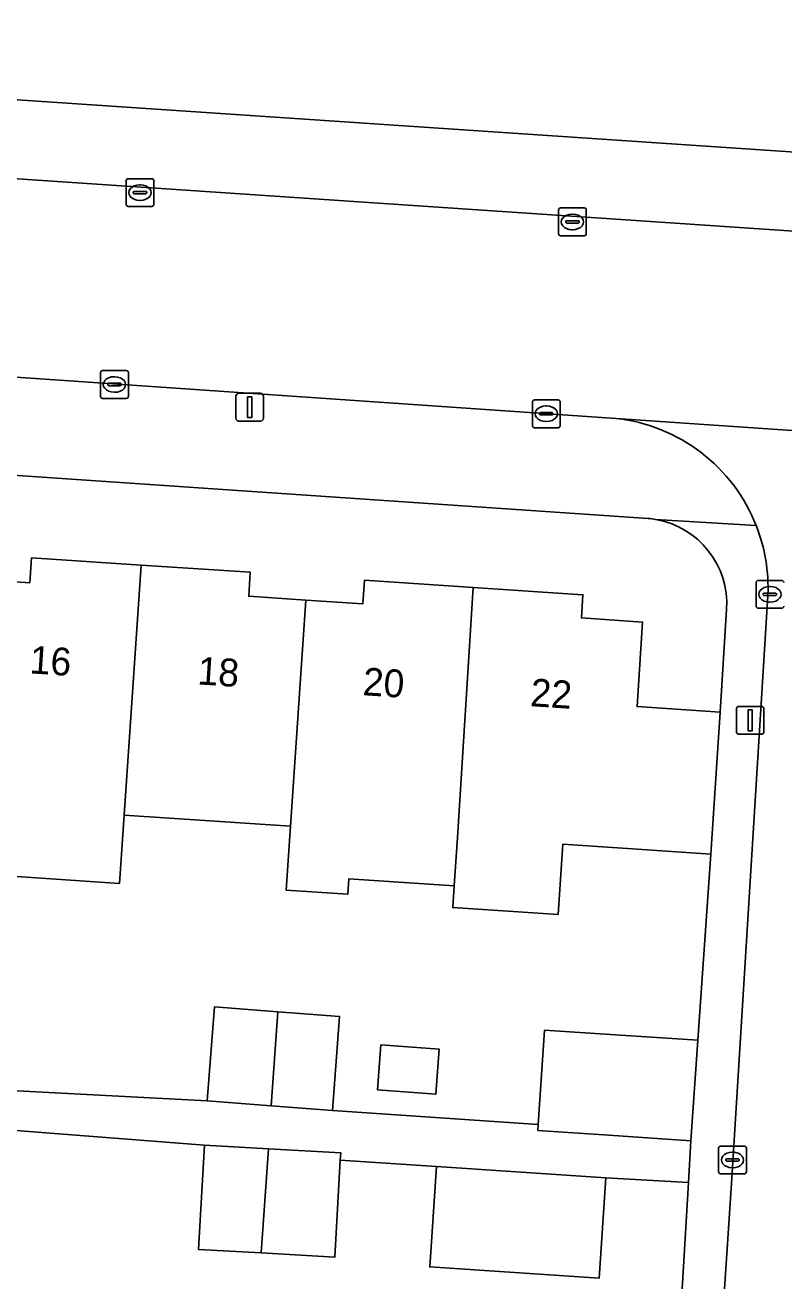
# Model space of a CAD drawing. Extents: x 161848 to 162726, y 385382 to 386521.
# Drawn here: x 162288.48 to 162315.79, y 385563.71 to 385608.89 of the extents above; entities that cross this region are included whole.
import ezdxf

# ---------------------------------------------------------------- set-up
doc = ezdxf.new("R2010")
doc.units = 0
for name, color, linetype in [('IMGEO_Erf', 7, 'Continuous'), ('IMGEO_Groenvoorziening', 7, 'Continuous'), ('IMGEO_Kolk', 7, 'Continuous'), ('IMGEO_Lichtmast', 7, 'Continuous'), ('IMGEO_Muur', 7, 'Continuous'), ('IMGEO_Pand', 7, 'Continuous'), ('IMGEO_Pand_nummerreeks', 7, 'Continuous'), ('IMGEO_Rijbaan_lokaal_open', 7, 'Continuous'), ('IMGEO_Voetpad_open', 7, 'Continuous')]:
    doc.layers.add(name, color=color, linetype=linetype)

msp = doc.modelspace()

# ---------------------------------------------------------------- linework, layer by layer
at = {"layer": 'IMGEO_Erf'}
for points in [[(162310.902, 385591.138), (162245.477, 385595.597), (162240.397, 385595.895)], [(162286.584, 385588.962), (162288.657, 385588.824), (162288.716, 385589.724), (162292.662, 385589.463), (162296.586, 385589.204), (162296.529, 385588.34), (162298.583, 385588.204), (162300.64, 385588.068), (162300.696, 385588.917), (162304.608, 385588.658), (162308.555, 385588.397), (162308.499, 385587.559), (162310.703, 385587.413), (162310.502, 385584.37), (162313.495, 385584.171), (162313.724, 385587.868)], [(162287.968, 385570.566), (162295.039, 385570.185), (162295.298, 385573.567), (162297.573, 385573.393), (162299.802, 385573.222), (162299.543, 385569.841), (162306.95, 385569.344), (162307.175, 385572.737), (162309.726, 385572.567), (162312.69, 385572.369), (162313.157, 385579.065), (162310.164, 385579.263), (162307.829, 385579.417), (162307.662, 385576.893), (162303.872, 385577.144), (162303.923, 385577.92), (162300.133, 385578.179), (162300.095, 385577.619), (162297.872, 385577.77), (162298.028, 385580.065), (162292.044, 385580.461), (162291.876, 385578.007), (162285.874, 385578.411)], [(162312.144, 385563.613), (162312.352, 385567.255), (162309.381, 385567.425), (162309.141, 385563.813), (162303.044, 385564.218), (162303.284, 385567.83), (162299.826, 385568.05), (162299.633, 385564.57), (162296.983, 385564.717), (162294.726, 385564.842), (162294.934, 385568.591), (162287.846, 385569.148)]]:
    msp.add_lwpolyline(points, dxfattribs=at)
msp.add_lwpolyline([(162301.285, 385572.204), (162303.384, 385572.044), (162303.26, 385570.426), (162301.161, 385570.586)], close=True, dxfattribs=at)
for centre, radius, start, end in [((162310.649, 385588.037), 3.112, 80.3164, 85.3291), ((162310.65, 385588.068), 3.08, 356.271, 80.2496)]:
    msp.add_arc(centre, radius, start, end, dxfattribs=at)
at = {"layer": 'IMGEO_Groenvoorziening'}
msp.add_lwpolyline([(162313.914, 385618.371), (162310.525, 385618.197), (162307.227, 385618.391), (162299.207, 385618.52), (162290.024, 385619.62), (162287.372, 385623.112), (162282.522, 385621.172), (162278.641, 385622.853), (162272.521, 385624.409), (162263.398, 385624.644), (162261.506, 385623.382), (162259.85, 385621.49), (162259.535, 385620.15), (162259.693, 385616.365), (162261.033, 385614.788), (162265.291, 385613.054), (162271.835, 385611.556), (162272.639, 385611.354), (162274.554, 385609.13), (162276.436, 385606.992), (162319.231, 385604.108), (162319.8, 385609.337), (162317.424, 385614.541)], close=True, dxfattribs=at)
at = {"layer": 'IMGEO_Kolk'}
for p, q in [((162292.118, 385602.436), (162292.118, 385603.288)), ((162292.193, 385603.362), (162293.045, 385603.362)), ((162292.606, 385603.142), (162292.631, 385603.142)), ((162293.119, 385603.288), (162293.119, 385602.436)), ((162292.377, 385602.856), (162292.377, 385602.868)), ((162292.815, 385602.819), (162292.417, 385602.819)), ((162292.42, 385602.905), (162292.818, 385602.905)), ((162292.629, 385602.582), (162292.604, 385602.582)), ((162292.861, 385602.868), (162292.861, 385602.856)), ((162293.045, 385602.362), (162292.193, 385602.362)), ((162307.677, 385601.381), (162307.677, 385602.233)), ((162307.752, 385602.307), (162308.604, 385602.307)), ((162308.165, 385602.087), (162308.19, 385602.087)), ((162308.678, 385602.233), (162308.678, 385601.381)), ((162307.936, 385601.801), (162307.936, 385601.813)), ((162308.374, 385601.764), (162307.976, 385601.764)), ((162307.979, 385601.85), (162308.377, 385601.85)), ((162308.42, 385601.813), (162308.42, 385601.801)), ((162308.604, 385601.307), (162307.752, 385601.307)), ((162308.188, 385601.527), (162308.163, 385601.527)), ((162291.198, 385595.532), (162291.198, 385596.384)), ((162291.273, 385596.458), (162292.125, 385596.458)), ((162291.686, 385596.238), (162291.711, 385596.238)), ((162292.199, 385596.384), (162292.199, 385595.532)), ((162291.457, 385595.952), (162291.457, 385595.964)), ((162291.895, 385595.915), (162291.497, 385595.915)), ((162291.5, 385596.001), (162291.898, 385596.001)), ((162291.941, 385595.964), (162291.941, 385595.952)), ((162292.125, 385595.458), (162291.273, 385595.458)), ((162291.709, 385595.678), (162291.684, 385595.678)), ((162306.738, 385594.479), (162306.738, 385595.331)), ((162306.813, 385595.405), (162307.665, 385595.405)), ((162307.739, 385595.331), (162307.739, 385594.479)), ((162306.997, 385594.899), (162306.997, 385594.911)), ((162307.435, 385594.862), (162307.037, 385594.862)), ((162307.04, 385594.948), (162307.438, 385594.948)), ((162307.226, 385595.185), (162307.251, 385595.185)), ((162307.481, 385594.911), (162307.481, 385594.899)), ((162307.665, 385594.405), (162306.813, 385594.405)), ((162307.249, 385594.625), (162307.224, 385594.625)), ((162314.786, 385587.983), (162314.786, 385588.835)), ((162314.861, 385588.909), (162315.713, 385588.909)), ((162315.274, 385588.689), (162315.299, 385588.689)), ((162315.045, 385588.403), (162315.045, 385588.415)), ((162315.483, 385588.366), (162315.085, 385588.366)), ((162315.088, 385588.452), (162315.486, 385588.452)), ((162315.297, 385588.129), (162315.272, 385588.129)), ((162315.529, 385588.415), (162315.529, 385588.403)), ((162315.713, 385587.909), (162314.861, 385587.909)), ((162313.438, 385567.637), (162313.438, 385568.489)), ((162313.513, 385568.563), (162314.365, 385568.563)), ((162313.926, 385568.343), (162313.951, 385568.343)), ((162314.439, 385568.489), (162314.439, 385567.637)), ((162313.697, 385568.057), (162313.697, 385568.069)), ((162314.135, 385568.02), (162313.737, 385568.02)), ((162313.74, 385568.106), (162314.138, 385568.106)), ((162313.949, 385567.783), (162313.924, 385567.783)), ((162314.181, 385568.069), (162314.181, 385568.057)), ((162314.365, 385567.563), (162313.513, 385567.563))]:
    msp.add_line(p, q, dxfattribs=at)
for points in [[(162292.118, 385602.436), (162292.118, 385603.288)], [(162292.193, 385603.362), (162293.045, 385603.362)], [(162293.119, 385603.288), (162293.119, 385602.436)], [(162293.045, 385602.362), (162292.193, 385602.362)], [(162307.677, 385601.381), (162307.677, 385602.233)], [(162307.752, 385602.307), (162308.604, 385602.307)], [(162308.678, 385602.233), (162308.678, 385601.381)], [(162308.604, 385601.307), (162307.752, 385601.307)], [(162291.198, 385595.532), (162291.198, 385596.384)], [(162291.273, 385596.458), (162292.125, 385596.458)], [(162292.199, 385596.384), (162292.199, 385595.532)], [(162292.125, 385595.458), (162291.273, 385595.458)], [(162306.738, 385594.479), (162306.738, 385595.331)], [(162306.813, 385595.405), (162307.665, 385595.405)], [(162307.739, 385595.331), (162307.739, 385594.479)], [(162307.665, 385594.405), (162306.813, 385594.405)], [(162314.786, 385587.983), (162314.786, 385588.835)], [(162314.861, 385588.909), (162315.713, 385588.909)], [(162315.713, 385587.909), (162314.861, 385587.909)], [(162313.438, 385567.637), (162313.438, 385568.489)], [(162313.513, 385568.563), (162314.365, 385568.563)], [(162314.439, 385568.489), (162314.439, 385567.637)], [(162314.365, 385567.563), (162313.513, 385567.563)]]:
    msp.add_lwpolyline(points, dxfattribs=at)
for centre, radius, start, end in [((162292.195, 385603.286), 0.0765, 91.552, 178.448), ((162292.195, 385603.286), 0.0765, 91.552, 178.448), ((162293.043, 385603.286), 0.0765, 1.552, 88.448), ((162293.043, 385603.286), 0.0765, 1.552, 88.448), ((162292.417, 385602.865), 0.0403, 85.8775, 175.7526), ((162292.414, 385602.855), 0.0366, 178.938, 274.7102), ((162292.818, 385602.862), 0.043, 264.8664, 352.4533), ((162292.822, 385602.867), 0.0386, 1.7309, 96.639), ((162292.195, 385602.438), 0.0765, 181.552, 268.448), ((162292.195, 385602.438), 0.0765, 181.552, 268.448), ((162293.043, 385602.438), 0.0765, 271.552, 358.448), ((162293.043, 385602.438), 0.0765, 271.552, 358.448), ((162307.754, 385602.231), 0.0765, 91.552, 178.448), ((162307.754, 385602.231), 0.0765, 91.552, 178.448), ((162308.602, 385602.231), 0.0765, 1.552, 88.448), ((162308.602, 385602.231), 0.0765, 1.552, 88.448), ((162307.976, 385601.81), 0.0403, 85.8775, 175.7526), ((162307.973, 385601.8), 0.0366, 178.938, 274.7102), ((162308.377, 385601.807), 0.043, 264.8664, 352.4533), ((162308.381, 385601.812), 0.0386, 1.7309, 96.639), ((162307.754, 385601.383), 0.0765, 181.552, 268.448), ((162307.754, 385601.383), 0.0765, 181.552, 268.448), ((162308.602, 385601.383), 0.0765, 271.552, 358.448), ((162308.602, 385601.383), 0.0765, 271.552, 358.448), ((162291.275, 385596.382), 0.0765, 91.552, 178.448), ((162291.275, 385596.382), 0.0765, 91.552, 178.448), ((162292.123, 385596.382), 0.0765, 1.552, 88.448), ((162292.123, 385596.382), 0.0765, 1.552, 88.448), ((162291.497, 385595.961), 0.0403, 85.8775, 175.7526), ((162291.494, 385595.951), 0.0366, 178.938, 274.7102), ((162291.898, 385595.958), 0.043, 264.8664, 352.4533), ((162291.902, 385595.963), 0.0386, 1.7309, 96.639), ((162291.275, 385595.534), 0.0765, 181.552, 268.448), ((162291.275, 385595.534), 0.0765, 181.552, 268.448), ((162292.123, 385595.534), 0.0765, 271.552, 358.448), ((162292.123, 385595.534), 0.0765, 271.552, 358.448), ((162306.815, 385595.329), 0.0765, 91.552, 178.448), ((162306.815, 385595.329), 0.0765, 91.552, 178.448), ((162307.663, 385595.329), 0.0765, 1.552, 88.448), ((162307.663, 385595.329), 0.0765, 1.552, 88.448), ((162307.037, 385594.908), 0.0403, 85.8775, 175.7526), ((162307.034, 385594.898), 0.0366, 178.938, 274.7102), ((162307.438, 385594.905), 0.043, 264.8664, 352.4533), ((162307.442, 385594.91), 0.0386, 1.7309, 96.639), ((162306.815, 385594.481), 0.0765, 181.552, 268.448), ((162306.815, 385594.481), 0.0765, 181.552, 268.448), ((162307.663, 385594.481), 0.0765, 271.552, 358.448), ((162307.663, 385594.481), 0.0765, 271.552, 358.448), ((162314.863, 385588.833), 0.0765, 91.552, 178.448), ((162314.863, 385588.833), 0.0765, 91.552, 178.448), ((162315.711, 385588.833), 0.0765, 1.552, 88.448), ((162315.711, 385588.833), 0.0765, 1.552, 88.448), ((162315.085, 385588.412), 0.0403, 85.8775, 175.7526), ((162315.082, 385588.402), 0.0366, 178.938, 274.7102), ((162315.486, 385588.409), 0.043, 264.8664, 352.4533), ((162315.49, 385588.414), 0.0386, 1.7309, 96.639), ((162314.863, 385587.985), 0.0765, 181.552, 268.448), ((162314.863, 385587.985), 0.0765, 181.552, 268.448), ((162315.711, 385587.985), 0.0765, 271.552, 358.448), ((162315.711, 385587.985), 0.0765, 271.552, 358.448), ((162313.515, 385568.487), 0.0765, 91.552, 178.448), ((162313.515, 385568.487), 0.0765, 91.552, 178.448), ((162314.363, 385568.487), 0.0765, 1.552, 88.448), ((162314.363, 385568.487), 0.0765, 1.552, 88.448), ((162313.737, 385568.066), 0.0403, 85.8775, 175.7526), ((162313.734, 385568.056), 0.0366, 178.938, 274.7102), ((162314.138, 385568.063), 0.043, 264.8664, 352.4533), ((162314.142, 385568.068), 0.0386, 1.7309, 96.639), ((162313.515, 385567.639), 0.0765, 181.552, 268.448), ((162313.515, 385567.639), 0.0765, 181.552, 268.448), ((162314.363, 385567.639), 0.0765, 271.552, 358.448), ((162314.363, 385567.639), 0.0765, 271.552, 358.448)]:
    msp.add_arc(centre, radius, start, end, dxfattribs=at)
for centre, major_axis, ratio, start_param, end_param in [((162292.605, 385602.862), (-0.387, 0.002), 0.722429, 4.712389, 7.853982), ((162292.63, 385602.862), (-0.39, 0.002), 0.717154, 1.570796, 4.712389), ((162308.164, 385601.807), (-0.387, 0.002), 0.722429, 4.712389, 7.853982), ((162308.189, 385601.807), (-0.39, 0.002), 0.717154, 1.570796, 4.712389), ((162291.685, 385595.958), (-0.387, 0.002), 0.722429, 4.712389, 7.853982), ((162291.71, 385595.958), (-0.39, 0.002), 0.717154, 1.570796, 4.712389), ((162307.225, 385594.905), (-0.387, 0.002), 0.722429, 4.712389, 7.853982), ((162307.25, 385594.905), (-0.39, 0.002), 0.717154, 1.570796, 4.712389), ((162315.273, 385588.409), (-0.387, 0.002), 0.722429, 4.712389, 7.853982), ((162315.298, 385588.409), (-0.39, 0.002), 0.717154, 1.570796, 4.712389), ((162313.925, 385568.063), (-0.387, 0.002), 0.722429, 4.712389, 7.853982), ((162313.95, 385568.063), (-0.39, 0.002), 0.717154, 1.570796, 4.712389)]:
    msp.add_ellipse(centre, major_axis=major_axis, ratio=ratio, start_param=start_param, end_param=end_param, dxfattribs=at)
at = {"layer": 'IMGEO_Lichtmast'}
for p, q in [((162296.068, 385594.741), (162296.068, 385595.541)), ((162296.068, 385595.541), (162296.068, 385594.741)), ((162296.168, 385595.641), (162296.958, 385595.641)), ((162296.958, 385595.641), (162296.168, 385595.641)), ((162297.058, 385595.541), (162297.058, 385594.741)), ((162297.058, 385594.741), (162297.058, 385595.541)), ((162296.958, 385594.641), (162296.168, 385594.641)), ((162296.168, 385594.641), (162296.958, 385594.641)), ((162314.079, 385583.477), (162314.079, 385584.277)), ((162314.079, 385584.277), (162314.079, 385583.477)), ((162314.179, 385584.377), (162314.969, 385584.377)), ((162314.969, 385584.377), (162314.179, 385584.377)), ((162315.069, 385584.277), (162315.069, 385583.477)), ((162315.069, 385583.477), (162315.069, 385584.277)), ((162314.969, 385583.377), (162314.179, 385583.377)), ((162314.179, 385583.377), (162314.969, 385583.377))]:
    msp.add_line(p, q, dxfattribs=at)
for points in [[(162296.488, 385595.516), (162296.638, 385595.516), (162296.638, 385594.766), (162296.488, 385594.766), (162296.488, 385595.516)], [(162314.499, 385584.252), (162314.649, 385584.252), (162314.649, 385583.502), (162314.499, 385583.502), (162314.499, 385584.252)]]:
    msp.add_lwpolyline(points, dxfattribs=at)
for centre, start, end in [((162296.168, 385595.541), 90, 180), ((162296.168, 385595.541), 90, 180), ((162296.958, 385595.541), 0, 90), ((162296.958, 385595.541), 360, 90), ((162296.168, 385594.741), 180, 270), ((162296.168, 385594.741), 180, 270), ((162296.958, 385594.741), 270, 0), ((162296.958, 385594.741), 270, 0), ((162314.179, 385584.277), 90, 180), ((162314.179, 385584.277), 90, 180), ((162314.969, 385584.277), 0, 90), ((162314.969, 385584.277), 360, 90), ((162314.179, 385583.477), 180, 270), ((162314.179, 385583.477), 180, 270), ((162314.969, 385583.477), 270, 0), ((162314.969, 385583.477), 270, 0)]:
    msp.add_arc(centre, 0.1, start, end, dxfattribs=at)
at = {"layer": 'IMGEO_Muur'}
msp.add_lwpolyline([(162312.69, 385572.369), (162313.157, 385579.065)], dxfattribs=at)
at = {"layer": 'IMGEO_Pand'}
for points in [[(162292.662, 385589.463), (162288.716, 385589.724), (162288.657, 385588.824), (162286.584, 385588.962), (162286.039, 385580.858), (162285.874, 385578.411), (162291.876, 385578.007), (162292.044, 385580.461)], [(162292.044, 385580.461), (162298.028, 385580.065), (162298.583, 385588.204), (162296.529, 385588.34), (162296.586, 385589.204), (162292.662, 385589.463)], [(162304.608, 385588.658), (162300.696, 385588.917), (162300.64, 385588.068), (162298.583, 385588.204), (162298.028, 385580.065), (162297.872, 385577.77), (162300.095, 385577.619), (162300.133, 385578.179), (162303.923, 385577.92), (162304.039, 385579.668)], [(162313.495, 385584.171), (162310.502, 385584.37), (162310.703, 385587.413), (162308.499, 385587.559), (162308.555, 385588.397), (162304.608, 385588.658), (162304.039, 385579.668), (162303.923, 385577.92), (162303.872, 385577.144), (162307.662, 385576.893), (162307.829, 385579.417), (162310.164, 385579.263), (162313.157, 385579.065)], [(162297.573, 385573.393), (162295.298, 385573.567), (162295.039, 385570.185), (162297.342, 385570.009)], [(162297.573, 385573.393), (162297.342, 385570.009), (162299.543, 385569.841), (162299.802, 385573.222)], [(162312.69, 385572.369), (162309.726, 385572.567), (162307.175, 385572.737), (162306.95, 385569.344), (162306.935, 385569.123), (162309.486, 385568.953), (162312.438, 385568.756)], [(162301.161, 385570.586), (162303.26, 385570.426), (162303.384, 385572.044), (162301.285, 385572.204)], [(162296.983, 385564.717), (162297.237, 385568.463), (162294.934, 385568.591), (162294.726, 385564.842)], [(162299.826, 385568.05), (162299.841, 385568.319), (162297.237, 385568.463), (162296.983, 385564.717), (162299.633, 385564.57)], [(162309.381, 385567.425), (162303.284, 385567.83), (162303.044, 385564.218), (162309.141, 385563.813)]]:
    msp.add_lwpolyline(points, close=True, dxfattribs=at)
at = {"layer": 'IMGEO_Rijbaan_lokaal_open'}
for points in [[(162250.141, 385605.918), (162241.588, 385606.517), (162240.952, 385599.422), (162246.169, 385599.107), (162309.752, 385594.736), (162328.221, 385593.475)], [(162392.515, 385589.122), (162412.585, 385587.758), (162415.011, 385587.593), (162431.505, 385586.582), (162435.655, 385586.297), (162436.128, 385593.403), (162432.653, 385593.623), (162250.141, 385605.918)], [(162328.221, 385593.475), (162309.752, 385594.736)], [(162315.21, 385588.359), (162313.897, 385567.217), (162313.649, 385563.431), (162312.347, 385545.527)]]:
    msp.add_lwpolyline(points, dxfattribs=at)
for centre, radius, start, end in [((162309.08, 385588.638), 6.135, 21.4583, 83.7108), ((162309.087, 385588.636), 6.13, 357.4091, 21.4934)]:
    msp.add_arc(centre, radius, start, end, dxfattribs=at)
at = {"layer": 'IMGEO_Voetpad_open'}
for points in [[(162416.342, 385597.564), (162327.188, 385603.572), (162319.231, 385604.108), (162276.436, 385606.992), (162272.52, 385607.256), (162238.603, 385609.542), (162225.673, 385610.463), (162225.228, 385604.48), (162224.178, 385588.393)], [(162234.379, 385607.022), (162241.588, 385606.517), (162250.141, 385605.918), (162432.653, 385593.623), (162436.128, 385593.403), (162437.247, 385593.361)], [(162309.752, 385594.736), (162246.169, 385599.107), (162240.952, 385599.422)], [(162235.023, 385596.21), (162240.397, 385595.895), (162245.477, 385595.597), (162310.902, 385591.138)], [(162311.172, 385591.104), (162314.79, 385590.882)], [(162314.79, 385590.882), (162311.172, 385591.104)], [(162313.897, 385567.217), (162315.21, 385588.359)], [(162313.724, 385587.868), (162313.495, 385584.171), (162313.157, 385579.065), (162312.69, 385572.369), (162312.438, 385568.756), (162312.352, 385567.255), (162312.144, 385563.613), (162311.593, 385556.447), (162311.126, 385549.573), (162310.864, 385546.192), (162310.544, 385541.588)], [(162287.846, 385569.148), (162294.934, 385568.591), (162297.237, 385568.463), (162299.841, 385568.319), (162299.826, 385568.05), (162303.284, 385567.83), (162309.381, 385567.425), (162312.352, 385567.255), (162312.438, 385568.756), (162309.486, 385568.953), (162306.935, 385569.123), (162306.95, 385569.344), (162299.543, 385569.841), (162297.342, 385570.009), (162295.039, 385570.185), (162287.968, 385570.566)], [(162312.347, 385545.527), (162313.649, 385563.431), (162313.897, 385567.217)]]:
    msp.add_lwpolyline(points, dxfattribs=at)
for centre, radius, start, end in [((162309.08, 385588.638), 6.135, 21.4583, 83.7108), ((162310.649, 385588.037), 3.112, 80.3164, 85.3291), ((162310.65, 385588.068), 3.08, 356.271, 80.2496), ((162309.087, 385588.636), 6.13, 357.4091, 21.4934)]:
    msp.add_arc(centre, radius, start, end, dxfattribs=at)

# ---------------------------------------------------------------- texts
at = {"layer": 'IMGEO_Pand_nummerreeks'}
for s, rotation, p in [('16', 356.2471, (162288.628, 385585.569)), ('18', 356.2455, (162294.667, 385585.172)), ('20', 356.2471, (162300.613, 385584.783)), ('22', 356.2471, (162306.643, 385584.388))]:
    msp.add_text(s, height=1, rotation=rotation, dxfattribs=at).set_placement(p)

doc.saveas('drawing.dxf')
